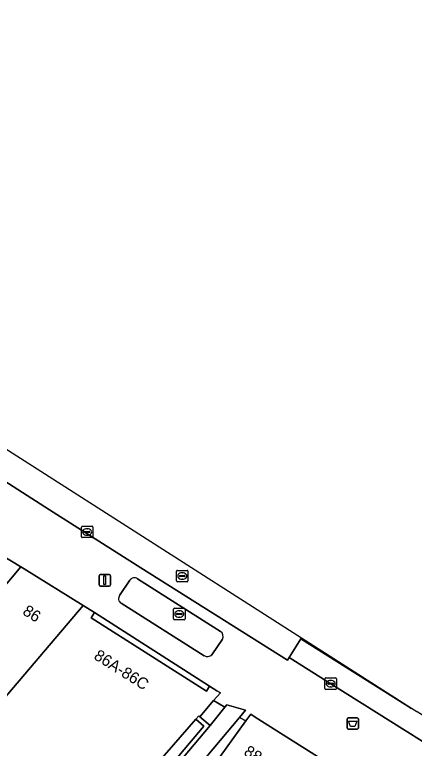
# Model space of a CAD drawing. Extents: x 161798 to 162385, y 382315 to 382833.
# Drawn here: x 162106.1 to 162141, y 382659.8 to 382723.8 of the extents above; entities that cross this region are included whole.
import ezdxf

# ---------------------------------------------------------------- set-up
doc = ezdxf.new("R2010")
doc.units = 0
for name, color, linetype in [('IMGEO_Afvalbak', 7, 'Continuous'), ('IMGEO_Erf', 7, 'Continuous'), ('IMGEO_Grasland_overig', 7, 'Continuous'), ('IMGEO_Groenvoorziening', 7, 'Continuous'), ('IMGEO_Haag', 7, 'Continuous'), ('IMGEO_Kolk', 7, 'Continuous'), ('IMGEO_Lichtmast', 7, 'Continuous'), ('IMGEO_Pand', 7, 'Continuous'), ('IMGEO_Pand_nummerreeks', 7, 'Continuous'), ('IMGEO_Rijbaan_lokaal_gesloten', 7, 'Continuous'), ('IMGEO_Rijbaan_lokaal_open', 7, 'Continuous'), ('IMGEO_Rioolput', 7, 'Continuous'), ('IMGEO_Voetpad_open', 7, 'Continuous')]:
    doc.layers.add(name, color=color, linetype=linetype)

msp = doc.modelspace()

# ---------------------------------------------------------------- linework, layer by layer
at = {"layer": 'IMGEO_Afvalbak'}
for p, q in [((162135.093, 382661.542), (162135.093, 382662.342)), ((162135.093, 382662.342), (162135.093, 382661.542)), ((162135.193, 382662.442), (162135.983, 382662.442)), ((162135.983, 382662.442), (162135.193, 382662.442)), ((162136.083, 382662.342), (162136.083, 382661.542)), ((162136.083, 382661.542), (162136.083, 382662.342)), ((162135.983, 382661.442), (162135.193, 382661.442)), ((162135.193, 382661.442), (162135.983, 382661.442))]:
    msp.add_line(p, q, dxfattribs=at)
msp.add_lwpolyline([(162135.236, 382662.156), (162135.94, 382662.156), (162135.791, 382661.686), (162135.385, 382661.686), (162135.236, 382662.156)], dxfattribs=at)
for centre, start, end in [((162135.193, 382662.342), 90, 180), ((162135.193, 382662.342), 90, 180), ((162135.983, 382662.342), 0, 90), ((162135.983, 382662.342), 360, 90), ((162135.193, 382661.542), 180, 270), ((162135.193, 382661.542), 180, 270), ((162135.983, 382661.542), 270, 0), ((162135.983, 382661.542), 270, 0)]:
    msp.add_arc(centre, 0.1, start, end, dxfattribs=at)
at = {"layer": 'IMGEO_Erf'}
msp.add_lwpolyline([(162113.034, 382671.627), (162112.749, 382671.175), (162122.807, 382664.757), (162123.097, 382665.212)], close=True, dxfattribs=at)
at = {"layer": 'IMGEO_Grasland_overig'}
msp.add_lwpolyline([(162107.896, 382646.361), (162112.73, 382649.402), (162123.146, 382661.769), (162122.238, 382662.535), (162122.144, 382662.616), (162121.881, 382662.313), (162122.583, 382661.721), (162112.464, 382649.707), (162107.688, 382646.703)], close=True, dxfattribs=at)
at = {"layer": 'IMGEO_Groenvoorziening'}
for points in [[(162116.129, 382674.443), (162115.23, 382673.109)], [(162124.054, 382669.986), (162116.792, 382674.572)], [(162115.353, 382672.454), (162122.621, 382667.865)], [(162123.295, 382667.949), (162124.212, 382669.308)]]:
    msp.add_lwpolyline(points, dxfattribs=at)
for points in [[(162121.881, 382662.313), (162113.889, 382653.134), (162113.749, 382653.246), (162106.192, 382649.16), (162107.688, 382646.703), (162112.464, 382649.707), (162122.583, 382661.721)], [(162123.491, 382658.338), (162126.268, 382662.17), (162125.705, 382662.471), (162113.737, 382648.232), (162109.486, 382645.543), (162110.247, 382644.31), (162111.973, 382645.388), (162115.796, 382649.068), (162116.194, 382648.694), (162116.22, 382648.724), (162116.246, 382648.753), (162117.475, 382650.02)]]:
    msp.add_lwpolyline(points, close=True, dxfattribs=at)
for centre, radius, start, end in [((162116.519, 382674.209), 0.454, 52.99972, 149.02124), ((162115.593, 382672.838), 0.453, 143.27874, 237.99226), ((162123.734, 382669.554), 0.538, 332.79513, 53.44086), ((162122.906, 382668.325), 0.541, 238.21916, 315.98902)]:
    msp.add_arc(centre, radius, start, end, dxfattribs=at)
at = {"layer": 'IMGEO_Haag'}
msp.add_lwpolyline([(162123.146, 382661.769), (162122.238, 382662.535), (162122.144, 382662.616), (162121.881, 382662.313), (162122.583, 382661.721), (162112.464, 382649.707), (162107.688, 382646.703), (162107.896, 382646.361), (162112.73, 382649.402)], close=True, dxfattribs=at)
at = {"layer": 'IMGEO_Kolk'}
for p, q in [((162111.899, 382678.239), (162111.899, 382679.091)), ((162111.974, 382679.165), (162112.826, 382679.165)), ((162112.387, 382678.945), (162112.412, 382678.945)), ((162112.9, 382679.091), (162112.9, 382678.239)), ((162112.158, 382678.659), (162112.158, 382678.671)), ((162112.596, 382678.622), (162112.198, 382678.622)), ((162112.201, 382678.708), (162112.599, 382678.708)), ((162112.41, 382678.385), (162112.385, 382678.385)), ((162112.642, 382678.671), (162112.642, 382678.659)), ((162112.826, 382678.165), (162111.974, 382678.165)), ((162133.166, 382664.992), (162133.166, 382665.844)), ((162133.241, 382665.918), (162134.093, 382665.918)), ((162133.425, 382665.412), (162133.425, 382665.424)), ((162133.468, 382665.461), (162133.866, 382665.461)), ((162133.654, 382665.698), (162133.679, 382665.698)), ((162133.909, 382665.424), (162133.909, 382665.412)), ((162134.167, 382665.844), (162134.167, 382664.992)), ((162134.093, 382664.918), (162133.241, 382664.918)), ((162133.863, 382665.375), (162133.465, 382665.375)), ((162133.677, 382665.138), (162133.652, 382665.138))]:
    msp.add_line(p, q, dxfattribs=at)
for points in [[(162111.899, 382678.239), (162111.899, 382679.091)], [(162111.974, 382679.165), (162112.826, 382679.165)], [(162112.9, 382679.091), (162112.9, 382678.239)], [(162112.826, 382678.165), (162111.974, 382678.165)], [(162133.166, 382664.992), (162133.166, 382665.844)], [(162133.241, 382665.918), (162134.093, 382665.918)], [(162134.167, 382665.844), (162134.167, 382664.992)], [(162134.093, 382664.918), (162133.241, 382664.918)]]:
    msp.add_lwpolyline(points, dxfattribs=at)
for centre, radius, start, end in [((162111.976, 382679.089), 0.0765, 91.55205, 178.44795), ((162111.976, 382679.089), 0.0765, 91.55205, 178.44795), ((162112.824, 382679.089), 0.0765, 1.55205, 88.44795), ((162112.824, 382679.089), 0.0765, 1.55205, 88.44795), ((162111.976, 382678.241), 0.0765, 181.55205, 268.44795), ((162111.976, 382678.241), 0.0765, 181.55205, 268.44795), ((162112.198, 382678.668), 0.0403, 85.87752, 175.75265), ((162112.195, 382678.658), 0.0366, 178.93798, 274.71019), ((162112.599, 382678.665), 0.043, 264.86636, 352.45326), ((162112.603, 382678.67), 0.0386, 1.73085, 96.63898), ((162112.824, 382678.241), 0.0765, 271.55205, 358.44795), ((162112.824, 382678.241), 0.0765, 271.55205, 358.44795), ((162133.243, 382665.842), 0.0765, 91.55205, 178.44795), ((162133.243, 382665.842), 0.0765, 91.55205, 178.44795), ((162133.465, 382665.421), 0.0403, 85.87752, 175.75265), ((162133.462, 382665.411), 0.0366, 178.93798, 274.71019), ((162133.866, 382665.418), 0.043, 264.86636, 352.45326), ((162133.87, 382665.423), 0.0386, 1.73085, 96.63898), ((162134.091, 382665.842), 0.0765, 1.55205, 88.44795), ((162134.091, 382665.842), 0.0765, 1.55205, 88.44795), ((162133.243, 382664.994), 0.0765, 181.55205, 268.44795), ((162133.243, 382664.994), 0.0765, 181.55205, 268.44795), ((162134.091, 382664.994), 0.0765, 271.55205, 358.44795), ((162134.091, 382664.994), 0.0765, 271.55205, 358.44795)]:
    msp.add_arc(centre, radius, start, end, dxfattribs=at)
for centre, major_axis, ratio, start_param, end_param in [((162112.386, 382678.665), (-0.387, 0.002), 0.722429, 4.712389, 7.853982), ((162112.411, 382678.665), (-0.39, 0.002), 0.717154, 1.570796, 4.712389), ((162133.653, 382665.418), (-0.387, 0.002), 0.722429, 4.712389, 7.853982), ((162133.678, 382665.418), (-0.39, 0.002), 0.717154, 1.570796, 4.712389)]:
    msp.add_ellipse(centre, major_axis=major_axis, ratio=ratio, start_param=start_param, end_param=end_param, dxfattribs=at)
at = {"layer": 'IMGEO_Lichtmast'}
for p, q in [((162113.437, 382674.044), (162113.437, 382674.844)), ((162113.437, 382674.844), (162113.437, 382674.044)), ((162113.537, 382674.944), (162114.327, 382674.944)), ((162114.327, 382674.944), (162113.537, 382674.944)), ((162114.427, 382674.844), (162114.427, 382674.044)), ((162114.427, 382674.044), (162114.427, 382674.844)), ((162114.327, 382673.944), (162113.537, 382673.944)), ((162113.537, 382673.944), (162114.327, 382673.944))]:
    msp.add_line(p, q, dxfattribs=at)
msp.add_lwpolyline([(162113.857, 382674.819), (162114.007, 382674.819), (162114.007, 382674.069), (162113.857, 382674.069), (162113.857, 382674.819)], dxfattribs=at)
for centre, start, end in [((162113.537, 382674.844), 90, 180), ((162113.537, 382674.844), 90, 180), ((162114.327, 382674.844), 0, 90), ((162114.327, 382674.844), 360, 90), ((162113.537, 382674.044), 180, 270), ((162113.537, 382674.044), 180, 270), ((162114.327, 382674.044), 270, 0), ((162114.327, 382674.044), 270, 0)]:
    msp.add_arc(centre, 0.1, start, end, dxfattribs=at)
at = {"layer": 'IMGEO_Pand'}
for points in [[(162106.594, 382675.618), (162104.136, 382677.116), (162103.949, 382677.238), (162087.494, 382688.013), (162080.055, 382677.948), (162078.981, 382678.576), (162074.525, 382674.387), (162072.358, 382671.028), (162072.648, 382670.851), (162072.703, 382670.936), (162073.412, 382672.036), (162074.251, 382671.491), (162074.142, 382671.323), (162090.218, 382660.88), (162092.518, 382659.386), (162094.953, 382661.964), (162096.171, 382663.253), (162097.075, 382664.32), (162097.929, 382665.328), (162098.773, 382666.323)], [(162106.889, 382675.435), (162106.594, 382675.618), (162098.773, 382666.323), (162103.042, 382662.591), (162104.436, 382663.341), (162112.042, 382672.242)], [(162125.839, 382642.364), (162135.279, 382657.327), (162127.075, 382662.507), (162126.69, 382662.75), (162126.268, 382662.17), (162123.491, 382658.338), (162126.567, 382656.399), (162124.821, 382653.63), (162127.804, 382651.749), (162123.01, 382644.148)]]:
    msp.add_lwpolyline(points, close=True, dxfattribs=at)
msp.add_lwpolyline([(162113.889, 382653.134), (162121.881, 382662.313), (162122.144, 382662.616), (162122.238, 382662.535), (162123.446, 382663.939), (162124.03, 382664.619), (162123.733, 382664.808), (162123.097, 382665.212), (162122.807, 382664.757), (162112.749, 382671.175), (162113.034, 382671.627), (162112.042, 382672.242), (162104.436, 382663.341), (162103.042, 382662.591), (162098.773, 382666.323), (162097.929, 382665.328), (162097.075, 382664.32), (162096.171, 382663.253), (162094.953, 382661.964), (162092.518, 382659.386)], dxfattribs=at)
at = {"layer": 'IMGEO_Rijbaan_lokaal_gesloten'}
msp.add_lwpolyline([(162140.733, 382663.262), (162131.072, 382669.325), (162130.048, 382667.707), (162133.667, 382665.418), (162148.157, 382656.334), (162149.174, 382657.964), (162141.217, 382662.958), (162141.182, 382662.975)], close=True, dxfattribs=at)
at = {"layer": 'IMGEO_Rijbaan_lokaal_open'}
for points in [[(162140.733, 382663.262), (162095.172, 382692.349), (162059.829, 382723.81), (162059.12, 382723.035), (162063.175, 382719.373), (162061.886, 382717.951), (162061.695, 382717.709), (162069.75, 382710.451), (162071.409, 382708.931), (162075.668, 382705.123)], [(162097.396, 382688.25), (162099.27, 382686.974), (162103.542, 382684.136), (162109.115, 382680.594), (162117.092, 382675.543), (162129.893, 382667.475), (162130.048, 382667.707), (162131.072, 382669.325), (162140.733, 382663.262)]]:
    msp.add_lwpolyline(points, dxfattribs=at)
at = {"layer": 'IMGEO_Rioolput'}
for p, q in [((162120.202, 382674.386), (162120.202, 382675.238)), ((162120.277, 382675.312), (162121.129, 382675.312)), ((162120.69, 382675.092), (162120.715, 382675.092)), ((162121.203, 382675.238), (162121.203, 382674.386)), ((162120.461, 382674.806), (162120.461, 382674.818)), ((162120.899, 382674.769), (162120.501, 382674.769)), ((162120.504, 382674.855), (162120.902, 382674.855)), ((162120.713, 382674.532), (162120.688, 382674.532)), ((162120.945, 382674.818), (162120.945, 382674.806)), ((162121.129, 382674.312), (162120.277, 382674.312)), ((162119.943, 382671.077), (162119.943, 382671.929)), ((162120.018, 382672.003), (162120.87, 382672.003)), ((162120.944, 382671.929), (162120.944, 382671.077)), ((162120.202, 382671.497), (162120.202, 382671.509)), ((162120.64, 382671.46), (162120.242, 382671.46)), ((162120.245, 382671.546), (162120.643, 382671.546)), ((162120.454, 382671.223), (162120.429, 382671.223)), ((162120.431, 382671.783), (162120.456, 382671.783)), ((162120.686, 382671.509), (162120.686, 382671.497)), ((162120.87, 382671.003), (162120.018, 382671.003))]:
    msp.add_line(p, q, dxfattribs=at)
for points in [[(162120.202, 382674.386), (162120.202, 382675.238)], [(162120.277, 382675.312), (162121.129, 382675.312)], [(162121.203, 382675.238), (162121.203, 382674.386)], [(162121.129, 382674.312), (162120.277, 382674.312)], [(162119.943, 382671.077), (162119.943, 382671.929)], [(162120.018, 382672.003), (162120.87, 382672.003)], [(162120.944, 382671.929), (162120.944, 382671.077)], [(162120.87, 382671.003), (162120.018, 382671.003)]]:
    msp.add_lwpolyline(points, dxfattribs=at)
for centre, radius, start, end in [((162120.279, 382675.236), 0.0765, 91.55205, 178.44795), ((162120.279, 382675.236), 0.0765, 91.55205, 178.44795), ((162121.127, 382675.236), 0.0765, 1.55205, 88.44795), ((162121.127, 382675.236), 0.0765, 1.55205, 88.44795), ((162120.279, 382674.388), 0.0765, 181.55205, 268.44795), ((162120.279, 382674.388), 0.0765, 181.55205, 268.44795), ((162120.501, 382674.815), 0.0403, 85.87752, 175.75265), ((162120.498, 382674.805), 0.0366, 178.93798, 274.71019), ((162120.902, 382674.812), 0.043, 264.86636, 352.45326), ((162120.906, 382674.817), 0.0386, 1.73085, 96.63898), ((162121.127, 382674.388), 0.0765, 271.55205, 358.44795), ((162121.127, 382674.388), 0.0765, 271.55205, 358.44795), ((162120.02, 382671.927), 0.0765, 91.55205, 178.44795), ((162120.02, 382671.927), 0.0765, 91.55205, 178.44795), ((162120.868, 382671.927), 0.0765, 1.55205, 88.44795), ((162120.868, 382671.927), 0.0765, 1.55205, 88.44795), ((162120.242, 382671.506), 0.0403, 85.87752, 175.75265), ((162120.239, 382671.496), 0.0366, 178.93798, 274.71019), ((162120.643, 382671.503), 0.043, 264.86636, 352.45326), ((162120.647, 382671.508), 0.0386, 1.73085, 96.63898), ((162120.02, 382671.079), 0.0765, 181.55205, 268.44795), ((162120.02, 382671.079), 0.0765, 181.55205, 268.44795), ((162120.868, 382671.079), 0.0765, 271.55205, 358.44795), ((162120.868, 382671.079), 0.0765, 271.55205, 358.44795)]:
    msp.add_arc(centre, radius, start, end, dxfattribs=at)
for centre, major_axis, ratio, start_param, end_param in [((162120.689, 382674.812), (-0.387, 0.002), 0.722429, 4.712389, 7.853982), ((162120.714, 382674.812), (-0.39, 0.002), 0.717154, 1.570796, 4.712389), ((162120.43, 382671.503), (-0.387, 0.002), 0.722429, 4.712389, 7.853982), ((162120.455, 382671.503), (-0.39, 0.002), 0.717154, 1.570796, 4.712389)]:
    msp.add_ellipse(centre, major_axis=major_axis, ratio=ratio, start_param=start_param, end_param=end_param, dxfattribs=at)
at = {"layer": 'IMGEO_Voetpad_open'}
for points in [[(162148.157, 382656.334), (162133.667, 382665.418), (162130.048, 382667.707), (162129.893, 382667.475), (162117.092, 382675.543), (162109.115, 382680.594), (162103.542, 382684.136)], [(162104.136, 382677.116), (162106.594, 382675.618), (162106.889, 382675.435), (162112.042, 382672.242), (162113.034, 382671.627), (162123.097, 382665.212), (162123.733, 382664.808), (162124.03, 382664.619), (162123.446, 382663.939), (162124.415, 382663.379), (162124.583, 382663.586), (162126.232, 382663.098), (162125.705, 382662.471), (162126.268, 382662.17), (162126.69, 382662.75), (162127.075, 382662.507), (162135.279, 382657.327)], [(162115.23, 382673.109), (162116.129, 382674.443)], [(162116.792, 382674.572), (162124.054, 382669.986)], [(162122.621, 382667.865), (162115.353, 382672.454)], [(162124.212, 382669.308), (162123.295, 382667.949)], [(162113.737, 382648.232), (162125.705, 382662.471), (162126.232, 382663.098), (162124.583, 382663.586), (162124.415, 382663.379), (162123.146, 382661.769), (162112.73, 382649.402)]]:
    msp.add_lwpolyline(points, dxfattribs=at)
msp.add_lwpolyline([(162123.146, 382661.769), (162124.415, 382663.379), (162123.446, 382663.939), (162122.238, 382662.535)], close=True, dxfattribs=at)
for centre, radius, start, end in [((162116.519, 382674.209), 0.454, 52.99972, 149.02124), ((162115.593, 382672.838), 0.453, 143.27874, 237.99226), ((162123.734, 382669.554), 0.538, 332.79513, 53.44086), ((162122.906, 382668.325), 0.541, 238.21916, 315.98902)]:
    msp.add_arc(centre, radius, start, end, dxfattribs=at)

# ---------------------------------------------------------------- texts
at = {"layer": 'IMGEO_Pand_nummerreeks'}
for s, rotation, p in [('86', 327.62112, (162106.684, 382671.523)), ('86A-86C', 327.68518, (162112.906, 382667.629)), ('88A-88B', 327.76501, (162126.002, 382659.26))]:
    msp.add_text(s, height=1, rotation=rotation, dxfattribs=at).set_placement(p)

doc.saveas('drawing.dxf')
